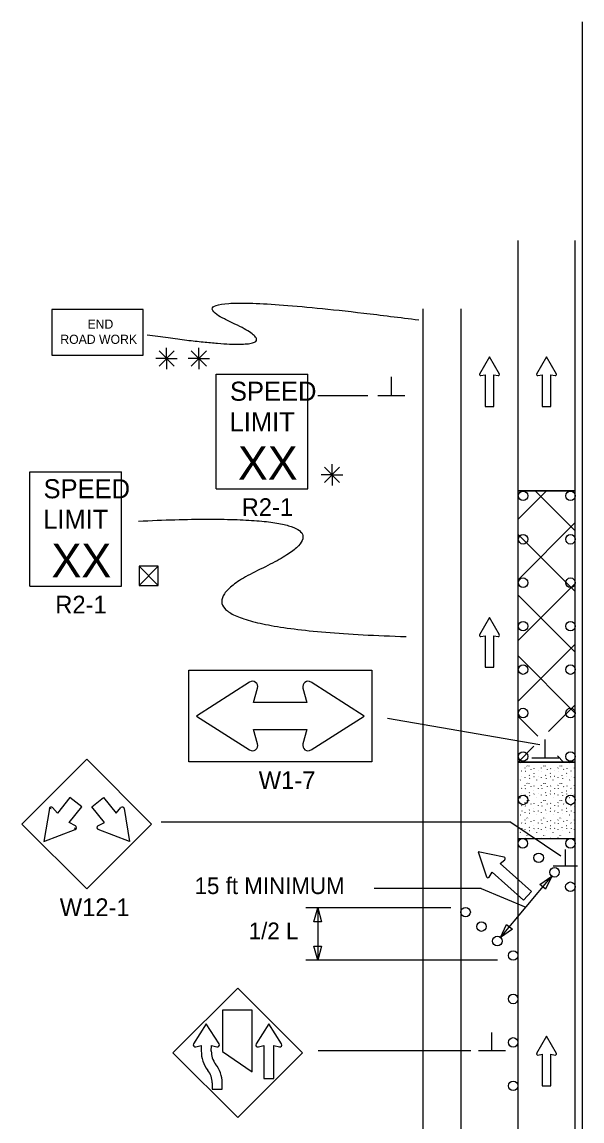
# Model space of a CAD drawing. Extents: x 16741 to 18482, y 7002 to 8333.
# Drawn here: x 16745.9 to 16980.7, y 7872.3 to 8333.1 of the extents above; entities that cross this region are included whole.
import ezdxf

# ---------------------------------------------------------------- set-up
doc = ezdxf.new("R2010")
doc.units = 0
for name, color, linetype in [('ALI_LEGAL_EX', 7, 'Continuous'), ('MT_SCRATCH_LEVEL_E', 7, 'Continuous'), ('PAVT_EDGE_EX', 7, 'Continuous'), ('TRAFFIC_SIGNS_PR', 7, 'Continuous'), ('TYPICAL_TEXT_DIMEN_PR', 7, 'Continuous')]:
    doc.layers.add(name, color=color, linetype=linetype)

msp = doc.modelspace()

# ---------------------------------------------------------------- linework, layer by layer
at = {"layer": 'ALI_LEGAL_EX'}
for p, q in [((16980.68, 8333.08), (16980.68, 7514.94)), ((16953.87, 7620.35), (16953.87, 8241.48)), ((16977.87, 7620.35), (16977.87, 8241.48))]:
    msp.add_line(p, q, dxfattribs=at)
for points in [[(16953.87, 8175.35), (16953.87, 8200.34)], [(16977.87, 8175.35), (16977.87, 8200.34)], [(16953.87, 8075.35), (16953.87, 8100.35)], [(16977.87, 8075.35), (16977.87, 8100.35)], [(16953.87, 7875.35), (16953.87, 7900.35)], [(16977.87, 7875.35), (16977.87, 7900.35)]]:
    msp.add_lwpolyline(points, dxfattribs=at)
at = {"layer": 'MT_SCRATCH_LEVEL_E'}
for p, q in [((16941.87, 8192.71), (16937.75, 8185.47)), ((16946.01, 8185.47), (16941.87, 8192.71)), ((16965.77, 8192.71), (16961.66, 8185.47)), ((16969.92, 8185.47), (16965.77, 8192.71)), ((16938.24, 8184.79), (16940.01, 8185.1)), ((16940.01, 8185.1), (16940.01, 8171.85)), ((16943.76, 8171.85), (16943.76, 8185.1)), ((16943.76, 8185.1), (16945.53, 8184.79)), ((16962.14, 8184.79), (16963.92, 8185.1)), ((16963.92, 8185.1), (16963.92, 8171.85)), ((16967.66, 8171.85), (16967.66, 8185.1)), ((16967.66, 8185.1), (16969.44, 8184.79)), ((16940.01, 8171.85), (16943.76, 8171.85)), ((16963.92, 8171.85), (16967.66, 8171.85)), ((16941.87, 8083.36), (16937.75, 8076.12)), ((16946.01, 8076.12), (16941.87, 8083.36)), ((16938.24, 8075.44), (16940.01, 8075.75)), ((16940.01, 8075.75), (16940.01, 8062.5)), ((16943.76, 8062.5), (16943.76, 8075.75)), ((16943.76, 8075.75), (16945.53, 8075.44)), ((16940.01, 8062.5), (16943.76, 8062.5)), ((16948, 7982.89), (16937.12, 7985.21)), ((16937.12, 7985.21), (16940.66, 7974.69)), ((16946.36, 7980.32), (16948.25, 7981.81)), ((16941.76, 7974.56), (16943.03, 7976.61)), ((16943.03, 7976.61), (16956.2, 7964.82)), ((16959.53, 7968.53), (16946.36, 7980.32)), ((16956.2, 7964.82), (16959.53, 7968.53)), ((16965.77, 7907.86), (16961.66, 7900.61)), ((16969.92, 7900.61), (16965.77, 7907.86)), ((16962.14, 7899.93), (16963.92, 7900.24)), ((16963.92, 7900.24), (16963.92, 7886.99)), ((16967.66, 7886.99), (16967.66, 7900.24)), ((16967.66, 7900.24), (16969.44, 7899.93)), ((16963.92, 7886.99), (16967.66, 7886.99))]:
    msp.add_line(p, q, dxfattribs=at)
for centre, radius, start, end in [((16938.16, 8185.25), 0.463, 150.4248, 279.9638), ((16945.6, 8185.25), 0.463, 260.0362, 29.7731), ((16962.07, 8185.25), 0.463, 150.4248, 279.9638), ((16969.51, 8185.25), 0.463, 260.0362, 29.7731), ((16938.16, 8075.9), 0.463, 150.4248, 279.9638), ((16945.6, 8075.9), 0.463, 260.0362, 29.7731), ((16947.86, 7982.29), 0.617, 308.2002, 77.9371), ((16941.24, 7974.9), 0.617, 198.5889, 328.1278), ((16962.07, 7900.39), 0.463, 150.4248, 279.9638), ((16969.51, 7900.39), 0.463, 260.0362, 29.7731)]:
    msp.add_arc(centre, radius, start, end, dxfattribs=at)
at = {"layer": 'PAVT_EDGE_EX'}
for p, q in [((16913.87, 8212.75), (16913.87, 7557.55)), ((16929.87, 8212.75), (16929.87, 7557.55)), ((16977.87, 8136.53), (16953.87, 8136.53)), ((16953.87, 8136.53), (16977.87, 8136.53)), ((16953.87, 8136.53), (16977.87, 8136.53)), ((16953.87, 8124.62), (16965.77, 8136.53)), ((16977.87, 8119.72), (16961.06, 8136.53)), ((16953.87, 8099.17), (16977.87, 8123.17)), ((16977.87, 8094.26), (16953.87, 8118.26)), ((16953.87, 8073.71), (16977.87, 8097.71)), ((16977.87, 8068.81), (16953.87, 8092.81)), ((16953.87, 8048.26), (16977.87, 8072.26)), ((16977.87, 8043.35), (16953.87, 8067.35)), ((16966.65, 8035.59), (16977.87, 8046.8)), ((16962.09, 8033.67), (16953.87, 8041.89)), ((16953.87, 8022.8), (16960.46, 8029.4)), ((16953.87, 8022.8), (16977.87, 8022.8)), ((16953.87, 8022.8), (16977.87, 8022.8)), ((16977.87, 8022.8), (16953.87, 8022.8)), ((16953.87, 8022.8), (16953.87, 8022.8)), ((16954.79, 8022.44), (16954.85, 8022.56)), ((16961.68, 8022.44), (16961.73, 8022.56)), ((16968.57, 8022.44), (16968.62, 8022.56)), ((16972.96, 8022.8), (16970.42, 8025.34)), ((16975.46, 8022.44), (16975.51, 8022.56)), ((16955.36, 8019.12), (16955.42, 8019.04)), ((16956.81, 8020.25), (16956.87, 8020.36)), ((16956.89, 8018.98), (16956.94, 8018.9)), ((16957.58, 8021.21), (16957.63, 8021.13)), ((16958.31, 8021.18), (16958.37, 8021.1)), ((16959.18, 8019.8), (16959.24, 8019.72)), ((16960.46, 8018.06), (16960.51, 8017.98)), ((16960.63, 8019.95), (16960.68, 8020.07)), ((16962.25, 8019.12), (16962.3, 8019.04)), ((16963.7, 8020.25), (16963.75, 8020.36)), ((16963.78, 8018.98), (16963.83, 8018.9)), ((16964.47, 8021.21), (16964.52, 8021.13)), ((16965.2, 8021.18), (16965.25, 8021.1)), ((16966.07, 8019.8), (16966.12, 8019.72)), ((16967.35, 8018.06), (16967.4, 8017.98)), ((16967.52, 8019.95), (16967.57, 8020.07)), ((16969.14, 8019.12), (16969.19, 8019.04)), ((16970.59, 8020.25), (16970.64, 8020.36)), ((16970.67, 8018.98), (16970.72, 8018.9)), ((16971.35, 8021.21), (16971.4, 8021.13)), ((16972.09, 8021.18), (16972.14, 8021.1)), ((16972.96, 8019.8), (16973.01, 8019.72)), ((16974.24, 8018.06), (16974.29, 8017.98)), ((16974.41, 8019.95), (16974.46, 8020.07)), ((16976.03, 8019.12), (16976.08, 8019.04)), ((16977.48, 8020.25), (16977.53, 8020.36)), ((16977.56, 8018.98), (16977.61, 8018.9)), ((16954.79, 8015.16), (16954.85, 8015.28)), ((16955.41, 8016.91), (16955.46, 8016.83)), ((16956.69, 8016.34), (16956.71, 8016.22)), ((16957.58, 8013.92), (16957.63, 8013.85)), ((16958.31, 8013.89), (16958.37, 8013.82)), ((16958.53, 8017.19), (16958.59, 8017.31)), ((16958.72, 8015.99), (16958.78, 8015.91)), ((16960.5, 8016.66), (16960.55, 8016.78)), ((16961.68, 8015.16), (16961.73, 8015.28)), ((16962.3, 8016.91), (16962.35, 8016.83)), ((16963.58, 8016.34), (16963.59, 8016.22)), ((16964.47, 8013.92), (16964.52, 8013.85)), ((16965.2, 8013.89), (16965.25, 8013.82)), ((16965.42, 8017.19), (16965.47, 8017.31)), ((16965.61, 8015.99), (16965.66, 8015.91)), ((16967.39, 8016.66), (16967.44, 8016.78)), ((16968.57, 8015.16), (16968.62, 8015.28)), ((16969.19, 8016.91), (16969.24, 8016.83)), ((16970.47, 8016.34), (16970.48, 8016.22)), ((16971.35, 8013.92), (16971.4, 8013.85)), ((16972.09, 8013.89), (16972.14, 8013.82)), ((16972.31, 8017.19), (16972.36, 8017.31)), ((16972.5, 8015.99), (16972.55, 8015.91)), ((16974.28, 8016.66), (16974.33, 8016.78)), ((16975.46, 8015.16), (16975.51, 8015.28)), ((16976.07, 8016.91), (16976.13, 8016.83)), ((16977.36, 8016.34), (16977.37, 8016.22)), ((16955.36, 8011.84), (16955.42, 8011.76)), ((16955.41, 8009.63), (16955.46, 8009.55)), ((16956.69, 8009.05), (16956.71, 8008.93)), ((16956.81, 8012.96), (16956.87, 8013.08)), ((16956.89, 8011.7), (16956.94, 8011.62)), ((16958.53, 8009.91), (16958.59, 8010.02)), ((16958.72, 8008.71), (16958.78, 8008.63)), ((16959.18, 8012.51), (16959.24, 8012.44)), ((16960.46, 8010.78), (16960.51, 8010.7)), ((16960.5, 8009.38), (16960.55, 8009.49)), ((16960.63, 8012.66), (16960.68, 8012.78)), ((16962.25, 8011.84), (16962.3, 8011.76)), ((16962.3, 8009.63), (16962.35, 8009.55)), ((16963.58, 8009.05), (16963.59, 8008.93)), ((16963.7, 8012.96), (16963.75, 8013.08)), ((16963.78, 8011.7), (16963.83, 8011.62)), ((16965.42, 8009.91), (16965.47, 8010.02)), ((16965.61, 8008.71), (16965.66, 8008.63)), ((16966.07, 8012.51), (16966.12, 8012.44)), ((16967.35, 8010.78), (16967.4, 8010.7)), ((16967.39, 8009.38), (16967.44, 8009.49)), ((16967.52, 8012.66), (16967.57, 8012.78)), ((16969.14, 8011.84), (16969.19, 8011.76)), ((16969.19, 8009.63), (16969.24, 8009.55)), ((16970.47, 8009.05), (16970.48, 8008.93)), ((16970.59, 8012.96), (16970.64, 8013.08)), ((16970.67, 8011.7), (16970.72, 8011.62)), ((16972.31, 8009.91), (16972.36, 8010.02)), ((16972.5, 8008.71), (16972.55, 8008.63)), ((16972.96, 8012.51), (16973.01, 8012.44)), ((16974.24, 8010.78), (16974.29, 8010.7)), ((16974.28, 8009.38), (16974.33, 8009.49)), ((16974.41, 8012.66), (16974.46, 8012.78)), ((16976.03, 8011.84), (16976.08, 8011.76)), ((16976.07, 8009.63), (16976.13, 8009.55)), ((16977.36, 8009.05), (16977.37, 8008.93)), ((16977.48, 8012.96), (16977.53, 8013.08)), ((16977.56, 8011.7), (16977.61, 8011.62)), ((16954.79, 8007.87), (16954.85, 8007.99)), ((16955.36, 8004.55), (16955.42, 8004.47)), ((16956.81, 8005.68), (16956.87, 8005.79)), ((16956.89, 8004.41), (16956.94, 8004.33)), ((16957.58, 8006.64), (16957.63, 8006.56)), ((16958.31, 8006.61), (16958.37, 8006.53)), ((16959.18, 8005.23), (16959.24, 8005.15)), ((16960.63, 8005.38), (16960.68, 8005.5)), ((16961.68, 8007.87), (16961.73, 8007.99)), ((16962.25, 8004.55), (16962.3, 8004.47)), ((16963.7, 8005.68), (16963.75, 8005.79)), ((16963.78, 8004.41), (16963.83, 8004.33)), ((16964.47, 8006.64), (16964.52, 8006.56)), ((16965.2, 8006.61), (16965.25, 8006.53)), ((16966.07, 8005.23), (16966.12, 8005.15)), ((16967.52, 8005.38), (16967.57, 8005.5)), ((16968.57, 8007.87), (16968.62, 8007.99)), ((16969.14, 8004.55), (16969.19, 8004.47)), ((16970.59, 8005.68), (16970.64, 8005.79)), ((16970.67, 8004.41), (16970.72, 8004.33)), ((16971.35, 8006.64), (16971.4, 8006.56)), ((16972.09, 8006.61), (16972.14, 8006.53)), ((16972.96, 8005.23), (16973.01, 8005.15)), ((16974.41, 8005.38), (16974.46, 8005.5)), ((16975.46, 8007.87), (16975.51, 8007.99)), ((16976.03, 8004.55), (16976.08, 8004.47)), ((16977.48, 8005.68), (16977.53, 8005.79)), ((16977.56, 8004.41), (16977.61, 8004.33)), ((16954.79, 8000.59), (16954.85, 8000.71)), ((16955.41, 8002.34), (16955.46, 8002.26)), ((16956.69, 8001.77), (16956.71, 8001.65)), ((16958.53, 8002.62), (16958.59, 8002.74)), ((16958.72, 8001.42), (16958.78, 8001.35)), ((16960.46, 8003.49), (16960.51, 8003.41)), ((16960.5, 8002.09), (16960.55, 8002.21)), ((16961.68, 8000.59), (16961.73, 8000.71)), ((16962.3, 8002.34), (16962.35, 8002.26)), ((16963.58, 8001.77), (16963.59, 8001.65)), ((16965.42, 8002.62), (16965.47, 8002.74)), ((16965.61, 8001.42), (16965.66, 8001.35)), ((16967.35, 8003.49), (16967.4, 8003.41)), ((16967.39, 8002.09), (16967.44, 8002.21)), ((16968.57, 8000.59), (16968.62, 8000.71)), ((16969.19, 8002.34), (16969.24, 8002.26)), ((16970.47, 8001.77), (16970.48, 8001.65)), ((16972.31, 8002.62), (16972.36, 8002.74)), ((16972.5, 8001.42), (16972.55, 8001.35)), ((16974.24, 8003.49), (16974.29, 8003.41)), ((16974.28, 8002.09), (16974.33, 8002.21)), ((16975.46, 8000.59), (16975.51, 8000.71)), ((16976.07, 8002.34), (16976.13, 8002.26)), ((16977.36, 8001.77), (16977.37, 8001.65)), ((16955.36, 7997.27), (16955.42, 7997.19)), ((16955.41, 7995.06), (16955.46, 7994.98)), ((16956.81, 7998.39), (16956.87, 7998.51)), ((16956.89, 7997.13), (16956.94, 7997.05)), ((16957.58, 7999.35), (16957.63, 7999.28)), ((16958.31, 7999.32), (16958.37, 7999.24)), ((16958.53, 7995.34), (16958.59, 7995.45)), ((16959.18, 7997.94), (16959.24, 7997.87)), ((16960.46, 7996.21), (16960.51, 7996.13)), ((16960.5, 7994.81), (16960.55, 7994.92)), ((16960.63, 7998.1), (16960.68, 7998.21)), ((16962.25, 7997.27), (16962.3, 7997.19)), ((16962.3, 7995.06), (16962.35, 7994.98)), ((16963.7, 7998.39), (16963.75, 7998.51)), ((16963.78, 7997.13), (16963.83, 7997.05)), ((16964.47, 7999.35), (16964.52, 7999.28)), ((16965.2, 7999.32), (16965.25, 7999.24)), ((16965.42, 7995.34), (16965.47, 7995.45)), ((16966.07, 7997.94), (16966.12, 7997.87)), ((16967.35, 7996.21), (16967.4, 7996.13)), ((16967.39, 7994.81), (16967.44, 7994.92)), ((16967.52, 7998.1), (16967.57, 7998.21)), ((16969.14, 7997.27), (16969.19, 7997.19)), ((16969.19, 7995.06), (16969.24, 7994.98)), ((16970.59, 7998.39), (16970.64, 7998.51)), ((16970.67, 7997.13), (16970.72, 7997.05)), ((16971.35, 7999.35), (16971.4, 7999.28)), ((16972.09, 7999.32), (16972.14, 7999.24)), ((16972.31, 7995.34), (16972.36, 7995.45)), ((16972.96, 7997.94), (16973.01, 7997.87)), ((16974.24, 7996.21), (16974.29, 7996.13)), ((16974.28, 7994.81), (16974.33, 7994.92)), ((16974.41, 7998.1), (16974.46, 7998.21)), ((16976.03, 7997.27), (16976.08, 7997.19)), ((16976.07, 7995.06), (16976.13, 7994.98)), ((16977.48, 7998.39), (16977.53, 7998.51)), ((16977.56, 7997.13), (16977.61, 7997.05)), ((16953.87, 7990.74), (16977.87, 7990.74)), ((16953.87, 7990.74), (16977.87, 7990.74)), ((16954.79, 7993.3), (16954.85, 7993.42)), ((16956.69, 7994.48), (16956.71, 7994.36)), ((16956.81, 7991.11), (16956.87, 7991.22)), ((16957.58, 7992.07), (16957.63, 7991.99)), ((16958.31, 7992.04), (16958.37, 7991.96)), ((16958.72, 7994.14), (16958.78, 7994.06)), ((16960.63, 7990.81), (16960.68, 7990.93)), ((16961.68, 7993.3), (16961.73, 7993.42)), ((16963.58, 7994.48), (16963.59, 7994.36)), ((16963.7, 7991.11), (16963.75, 7991.22)), ((16964.47, 7992.07), (16964.52, 7991.99)), ((16965.2, 7992.04), (16965.25, 7991.96)), ((16965.61, 7994.14), (16965.66, 7994.06)), ((16967.52, 7990.81), (16967.57, 7990.93)), ((16968.57, 7993.3), (16968.62, 7993.42)), ((16970.47, 7994.48), (16970.48, 7994.36)), ((16970.59, 7991.11), (16970.64, 7991.22)), ((16971.35, 7992.07), (16971.4, 7991.99)), ((16972.09, 7992.04), (16972.14, 7991.96)), ((16972.5, 7994.14), (16972.55, 7994.06)), ((16974.41, 7990.81), (16974.46, 7990.93)), ((16975.46, 7993.3), (16975.51, 7993.42)), ((16977.36, 7994.48), (16977.37, 7994.36)), ((16977.48, 7991.11), (16977.53, 7991.22))]:
    msp.add_line(p, q, dxfattribs=at)
at = {"layer": 'TRAFFIC_SIGNS_PR'}
for p, q in [((16827.3, 8185.4), (16865.7, 8185.4)), ((16827.3, 8137.4), (16827.3, 8185.4)), ((16865.7, 8137.4), (16865.7, 8185.4)), ((16749.14, 8144.52), (16787.54, 8144.52)), ((16749.14, 8096.52), (16749.14, 8144.52)), ((16787.54, 8096.52), (16787.54, 8144.52)), ((16827.3, 8137.4), (16865.7, 8137.4)), ((16749.14, 8096.52), (16787.54, 8096.52)), ((16773.02, 8023.93), (16745.87, 7996.78)), ((16800.17, 7996.78), (16773.02, 8023.93)), ((16758.11, 8003.18), (16757.34, 8003.31)), ((16745.87, 7996.78), (16773.02, 7969.63)), ((16767.92, 7995.31), (16768.21, 7994.56)), ((16773.02, 7969.63), (16800.17, 7996.78)), ((16836.3, 7928.04), (16809.14, 7900.89)), ((16863.45, 7900.89), (16836.3, 7928.04)), ((16809.14, 7900.89), (16836.3, 7873.74)), ((16836.3, 7873.74), (16863.45, 7900.89))]:
    msp.add_line(p, q, dxfattribs=at)
for points in [[(16758.34, 8193.37), (16796.74, 8193.37), (16796.74, 8212.57), (16758.34, 8212.57)], [(16892.57, 8022.89), (16815.77, 8022.89), (16815.77, 8061.29), (16892.57, 8061.29)], [(16829.99, 7918.82), (16829.99, 7901.48), (16842.39, 7892.86), (16842.39, 7918.82)]]:
    msp.add_lwpolyline(points, close=True, dxfattribs=at)
for points in [[(16841.28, 8056.29), (16818.97, 8042.09), (16841.28, 8027.88)], [(16867.05, 8027.89), (16889.37, 8042.09), (16867.05, 8056.29)], [(16863.69, 8053.81), (16865.36, 8047.69), (16842.97, 8047.69), (16844.65, 8053.81)], [(16844.65, 8030.37), (16842.97, 8036.49), (16865.36, 8036.49), (16863.69, 8030.37)], [(16768.31, 7996.01), (16765.63, 7997.44), (16770.9, 8003.99), (16765.98, 8007.96), (16760.7, 8001.4), (16758.7, 8003.7)], [(16777.74, 7996.01), (16780.41, 7997.44), (16775.14, 8003.99), (16780.06, 8007.96), (16785.34, 8001.4), (16787.35, 8003.7)], [(16757.34, 8003.31), (16755.08, 7989.42), (16768.21, 7994.56)], [(16788.71, 8003.31), (16790.96, 7989.42), (16777.83, 7994.56)], [(16828.49, 7904.6), (16823.16, 7912.96), (16817.83, 7904.59)], [(16854.71, 7904.59), (16849.39, 7912.96), (16844.06, 7904.59)], [(16818.77, 7903.33), (16821.06, 7903.96), (16821.06, 7901.73)], [(16825.25, 7901.63), (16825.26, 7903.96), (16827.56, 7903.33)], [(16845, 7903.33), (16847.29, 7903.96), (16847.29, 7890.16), (16851.49, 7890.16), (16851.49, 7903.96), (16853.79, 7903.33)], [(16825.63, 7888.28), (16825.62, 7885.63), (16829.82, 7885.63), (16829.82, 7888.28)]]:
    msp.add_lwpolyline(points, dxfattribs=at)
for centre in [(16955.97, 8134.41), (16975.84, 8134.41), (16955.97, 8116.19), (16975.84, 8116.19), (16955.97, 8097.98), (16975.84, 8097.98), (16955.97, 8079.76), (16975.84, 8079.76), (16955.97, 8061.55), (16975.84, 8061.55), (16955.97, 8043.33), (16975.84, 8043.33), (16955.97, 8025.12), (16975.84, 8025.12), (16955.97, 8006.91), (16975.84, 8006.91), (16955.85, 7988.7), (16975.84, 7988.69), (16962.5, 7982.64), (16969.15, 7976.57), (16975.8, 7970.5), (16931.86, 7959.87), (16938.51, 7953.81), (16945.16, 7947.74), (16951.8, 7941.67), (16951.8, 7941.67), (16951.8, 7923.46), (16951.8, 7905.24), (16951.8, 7887.04)]:
    msp.add_circle(centre, 2, dxfattribs=at)
for centre, radius, start, end in [((16842.49, 8054.4), 2.24, 344.6731, 122.4696), ((16865.84, 8054.4), 2.24, 57.5304, 195.3269), ((16842.49, 8029.77), 2.24, 237.5304, 15.3269), ((16865.84, 8029.78), 2.24, 164.6928, 302.4524), ((16758.11, 8003.17), 0.786, 41.8659, 170.0393), ((16787.93, 8003.17), 0.786, 9.9607, 138.1341), ((16767.92, 7995.31), 0.8, 291.4077, 61.1792), ((16778.12, 7995.31), 0.8, 118.8208, 248.5923), ((16818.54, 7904.14), 0.84, 147.5204, 285.3986), ((16827.78, 7904.14), 0.842, 254.6828, 32.2708), ((16824.78, 7893.21), 10.5, 74.68, 74.6808), ((16837.34, 7910.23), 10.5, 212.4569, 212.4665), ((16844.77, 7904.14), 0.841, 147.5497, 285.3316), ((16854.01, 7904.14), 0.839, 254.6778, 32.4665), ((16863.57, 7910.23), 10.5, 212.4569, 212.4665), ((16833.65, 7901.36), 12.59, 178.3293, 218.5427), ((16814.76, 7901.96), 10.5, 358.1894, 0.0048), ((16833.65, 7901.36), 8.4, 178.1936, 218.5465), ((16817.22, 7888.28), 8.4, 0, 38.5457), ((16817.22, 7888.28), 12.6, 0, 38.5422)]:
    msp.add_arc(centre, radius, start, end, dxfattribs=at)
msp.add_open_spline([(16798.34, 8201.97), (16866.67, 8191.88), (16799.95, 8222.7), (16912.21, 8208.18)], degree=2, dxfattribs=at)
at = {"layer": 'TYPICAL_TEXT_DIMEN_PR'}
for p, q in [((16803.33, 8195.14), (16809.7, 8188.76)), ((16809.7, 8195.14), (16803.33, 8188.76)), ((16806.51, 8191.95), (16806.51, 8196.4)), ((16816.83, 8195.14), (16823.21, 8188.76)), ((16823.21, 8195.14), (16816.83, 8188.76)), ((16820.02, 8191.95), (16820.02, 8196.4)), ((16806.51, 8191.95), (16801.98, 8191.95)), ((16806.51, 8191.95), (16809.7, 8191.95)), ((16806.51, 8191.95), (16810.99, 8191.95)), ((16806.51, 8191.95), (16806.51, 8187.45)), ((16820.02, 8191.95), (16815.49, 8191.95)), ((16820.02, 8191.95), (16823.21, 8191.95)), ((16820.02, 8191.95), (16824.5, 8191.95)), ((16820.02, 8191.95), (16820.02, 8187.45)), ((16900.74, 8176.53), (16900.74, 8184.31)), ((16900.74, 8176.53), (16900.74, 8184.31)), ((16869.89, 8176.53), (16890.87, 8176.53)), ((16878.29, 8176.53), (16890.87, 8176.53)), ((16895.12, 8176.53), (16906.37, 8176.53)), ((16895.12, 8176.53), (16906.37, 8176.53)), ((16875.87, 8143.19), (16875.87, 8147.65)), ((16875.87, 8143.19), (16871.34, 8143.19)), ((16872.69, 8146.38), (16879.06, 8140)), ((16879.06, 8146.38), (16872.69, 8140)), ((16875.87, 8143.19), (16879.06, 8143.19)), ((16875.87, 8143.19), (16880.35, 8143.19)), ((16875.87, 8143.19), (16875.87, 8138.69)), ((16794.95, 8104.85), (16802.95, 8096.85)), ((16794.95, 8096.85), (16802.95, 8104.85)), ((16962.95, 8030), (16899.17, 8041.09)), ((16965.27, 8024.49), (16965.27, 8032.27)), ((16959.65, 8024.49), (16970.9, 8024.49)), ((16950.82, 7997.53), (16804.26, 7997.53)), ((16950.82, 7997.53), (16971.74, 7983.49)), ((16973.69, 7979.14), (16973.69, 7986.14)), ((16978.76, 7979.14), (16968.63, 7979.14)), ((16946.52, 7949.2), (16967.96, 7974.96)), ((16963.01, 7971.46), (16967.96, 7974.96)), ((16967.96, 7974.96), (16965.42, 7969.45)), ((16938.38, 7969.79), (16893.52, 7969.79)), ((16938.38, 7969.79), (16957.12, 7961.94)), ((16964.21, 7970.45), (16963.01, 7971.46)), ((16965.42, 7969.45), (16964.21, 7970.45)), ((16925.69, 7961.65), (16864.87, 7961.65)), ((16868.3, 7955.78), (16869.87, 7961.65)), ((16869.87, 7961.65), (16871.44, 7955.78)), ((16869.87, 7961.65), (16869.87, 7939.67)), ((16869.87, 7955.78), (16868.3, 7955.78)), ((16871.44, 7955.78), (16869.87, 7955.78)), ((16946.52, 7949.2), (16949.06, 7954.71)), ((16949.06, 7954.71), (16950.27, 7953.71)), ((16950.27, 7953.71), (16951.48, 7952.7)), ((16951.48, 7952.7), (16946.52, 7949.2)), ((16869.87, 7939.67), (16868.3, 7945.53)), ((16868.3, 7945.53), (16869.87, 7945.53)), ((16869.87, 7945.53), (16871.44, 7945.53)), ((16871.44, 7945.53), (16869.87, 7939.67)), ((16945.24, 7939.67), (16864.87, 7939.67)), ((16942.91, 7901.67), (16942.91, 7909.46)), ((16934.08, 7901.67), (16870.09, 7901.67)), ((16948.53, 7901.67), (16937.28, 7901.67))]:
    msp.add_line(p, q, dxfattribs=at)
msp.add_lwpolyline([(16794.95, 8104.85), (16794.95, 8096.85), (16802.95, 8096.85), (16802.95, 8104.85)], close=True, dxfattribs=at)
msp.add_open_spline([(16794.75, 8123.82), (16898.47, 8128.7), (16793.86, 8078.94), (16906.89, 8075.38)], degree=2, dxfattribs=at)

# ---------------------------------------------------------------- texts
at = {"layer": 'TRAFFIC_SIGNS_PR'}
for s, height, p in [('END', 3.831, (16773.34, 8204.5)), ('ROAD WORK', 3.831, (16761.95, 8198.12)), ('SPEED', 8, (16833.07, 8174.26)), ('LIMIT', 8, (16832.91, 8161.46)), ('XX', 14.031, (16836.41, 8141.16)), ('SPEED', 8, (16754.91, 8133.38)), ('R2-1', 7.44, (16837.98, 8125.96)), ('LIMIT', 8, (16754.75, 8120.58)), ('XX', 14.031, (16758.26, 8100.27)), ('R2-1', 7.44, (16759.82, 8085.08)), ('W1-7', 7.44, (16845.13, 8011.45)), ('W12-1', 7.44, (16761.7, 7958.19))]:
    msp.add_text(s, height=height, dxfattribs=at).set_placement(p)
at = {"layer": 'TYPICAL_TEXT_DIMEN_PR'}
for s, p in [('15 ft MINIMUM', (16818.23, 7967.43)), ('1/2 L', (16840.94, 7948.49))]:
    msp.add_text(s, height=7, dxfattribs=at).set_placement(p)

doc.saveas('drawing.dxf')
